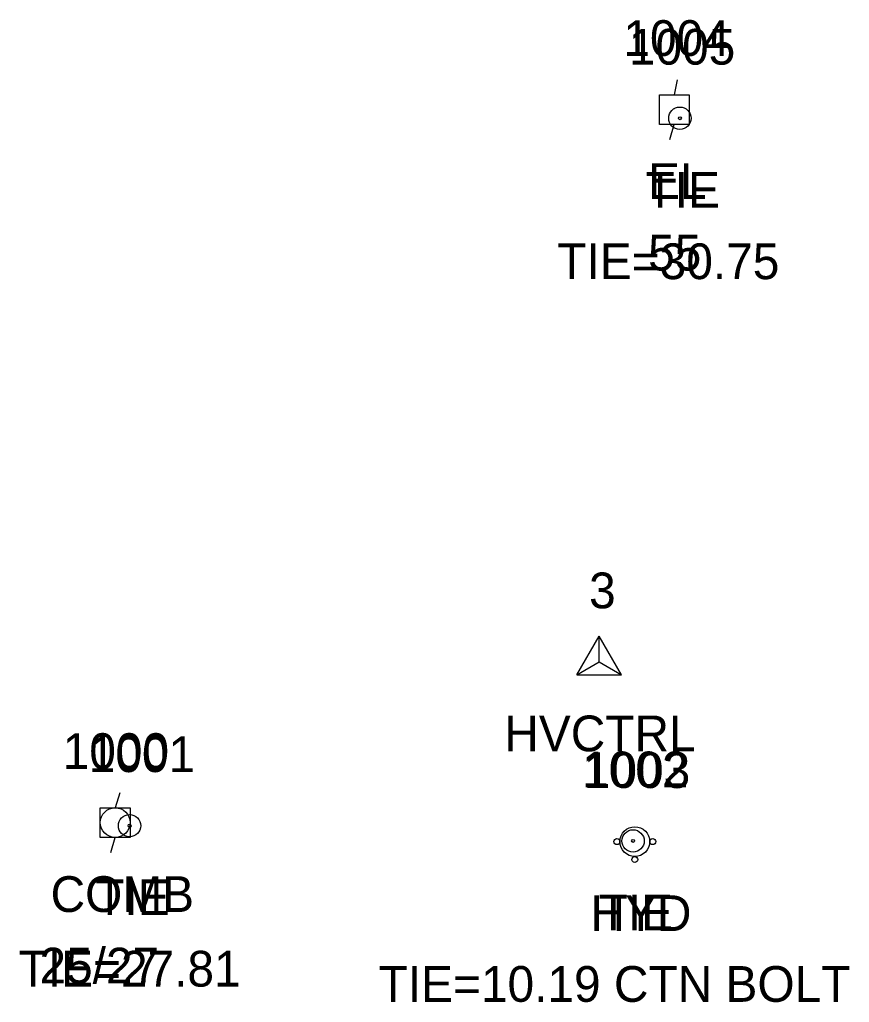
# Model space of a CAD drawing. Extents: x 1461855 to 1464118, y 556196 to 557441.
# Drawn here: x 1462333.8 to 1462380.2, y 557386 to 557441 of the extents above; entities that cross this region are included whole.
import ezdxf

# ---------------------------------------------------------------- set-up
doc = ezdxf.new("R2010")
doc.units = 0
for name, color, linetype in [('C_A', 7, 'Continuous'), ('C_C', 7, 'Continuous'), ('C_I', 7, 'Continuous'), ('CBP', 7, 'Continuous'), ('CPSM', 7, 'Continuous'), ('U_A', 7, 'Continuous'), ('U_C', 7, 'Continuous'), ('U_I', 7, 'Continuous'), ('UEPT', 7, 'Continuous'), ('UP', 7, 'Continuous'), ('UWFH', 7, 'Continuous')]:
    doc.layers.add(name, color=color, linetype=linetype)

msp = doc.modelspace()

# ---------------------------------------------------------------- linework, layer by layer
at = {"layer": 'CBP'}
for centre, radius in [((1462370.715, 557435.47), 0.625), ((1462370.715, 557435.47), 0.0833), ((1462339.945, 557395.898), 0.625), ((1462339.945, 557395.898), 0.0833), ((1462368.098, 557395.045), 0.625), ((1462368.098, 557395.045), 0.0833)]:
    msp.add_circle(centre, radius, dxfattribs=at)
at = {"layer": 'CPSM'}
for p, q in [((1462364.955, 557404.336), (1462366.205, 557406.501)), ((1462367.455, 557404.336), (1462366.205, 557406.501)), ((1462366.206, 557405.058), (1462366.205, 557406.501)), ((1462364.955, 557404.336), (1462366.206, 557405.058)), ((1462366.206, 557405.058), (1462366.206, 557405.058)), ((1462366.206, 557405.058), (1462367.455, 557404.336)), ((1462364.955, 557404.336), (1462367.455, 557404.336))]:
    msp.add_line(p, q, dxfattribs=at)
at = {"layer": 'UEPT'}
for p, q in [((1462370.572, 557437.622), (1462370.405, 557436.789)), ((1462369.572, 557435.122), (1462369.572, 557436.789)), ((1462369.572, 557436.789), (1462371.238, 557436.789)), ((1462371.238, 557436.789), (1462371.238, 557435.122)), ((1462370.405, 557435.956), (1462370.405, 557435.956)), ((1462371.238, 557435.122), (1462369.572, 557435.122)), ((1462370.155, 557434.289), (1462370.405, 557435.122))]:
    msp.add_line(p, q, dxfattribs=at)
at = {"layer": 'UP'}
for p, q in [((1462339.393, 557397.737), (1462339.143, 557396.904)), ((1462338.31, 557395.237), (1462338.31, 557396.904)), ((1462338.31, 557396.904), (1462339.977, 557396.904)), ((1462339.977, 557396.904), (1462339.977, 557395.237)), ((1462339.143, 557396.071), (1462339.143, 557396.071)), ((1462339.977, 557395.237), (1462338.31, 557395.237)), ((1462338.893, 557394.404), (1462339.143, 557395.237))]:
    msp.add_line(p, q, dxfattribs=at)
msp.add_circle((1462339.143, 557396.071), 0.833, dxfattribs=at)
at = {"layer": 'UWFH'}
msp.add_line((1462368.196, 557395.006), (1462368.196, 557395.006), dxfattribs=at)
for centre, radius in [((1462368.196, 557395.006), 0.833), ((1462367.196, 557395.006), 0.167), ((1462369.196, 557395.006), 0.167), ((1462368.196, 557394.006), 0.167)]:
    msp.add_circle(centre, radius, dxfattribs=at)

# ---------------------------------------------------------------- texts
at = {"layer": 'C_A'}
for s, p in [('TIE', (1462368.794, 557430.47)), ('HVCTRL', (1462360.899, 557400.058)), ('TIE', (1462338.024, 557390.898)), ('TIE', (1462366.177, 557390.045))]:
    msp.add_text(s, height=2, dxfattribs=at).set_placement(p)
at = {"layer": 'C_C'}
for s, p in [('TIE=30.75', (1462363.865, 557426.47)), ('TIE=27.81', (1462333.741, 557386.898)), ('TIE=10.19 CTN BOLT', (1462353.87, 557386.045))]:
    msp.add_text(s, height=2, dxfattribs=at).set_placement(p)
at = {"layer": 'C_I'}
for s, p in [('1005', (1462367.865, 557438.47)), ('3', (1462365.639, 557408.058)), ('1001', (1462337.662, 557398.898)), ('1002', (1462365.248, 557398.045))]:
    msp.add_text(s, height=2, dxfattribs=at).set_placement(p)
at = {"layer": 'U_A'}
for s, p in [('EL', (1462368.94, 557430.956)), ('COMB', (1462335.529, 557391.071)), ('HYD', (1462365.716, 557390.006))]:
    msp.add_text(s, height=2, dxfattribs=at).set_placement(p)
at = {"layer": 'U_C'}
for s, p in [('55', (1462368.94, 557426.956)), ('25/27', (1462334.907, 557387.071))]:
    msp.add_text(s, height=2, dxfattribs=at).set_placement(p)
at = {"layer": 'U_I'}
for s, p in [('1004', (1462367.555, 557438.956)), ('1000', (1462336.206, 557399.071)), ('1003', (1462365.346, 557398.006))]:
    msp.add_text(s, height=2, dxfattribs=at).set_placement(p)

doc.saveas('drawing.dxf')
